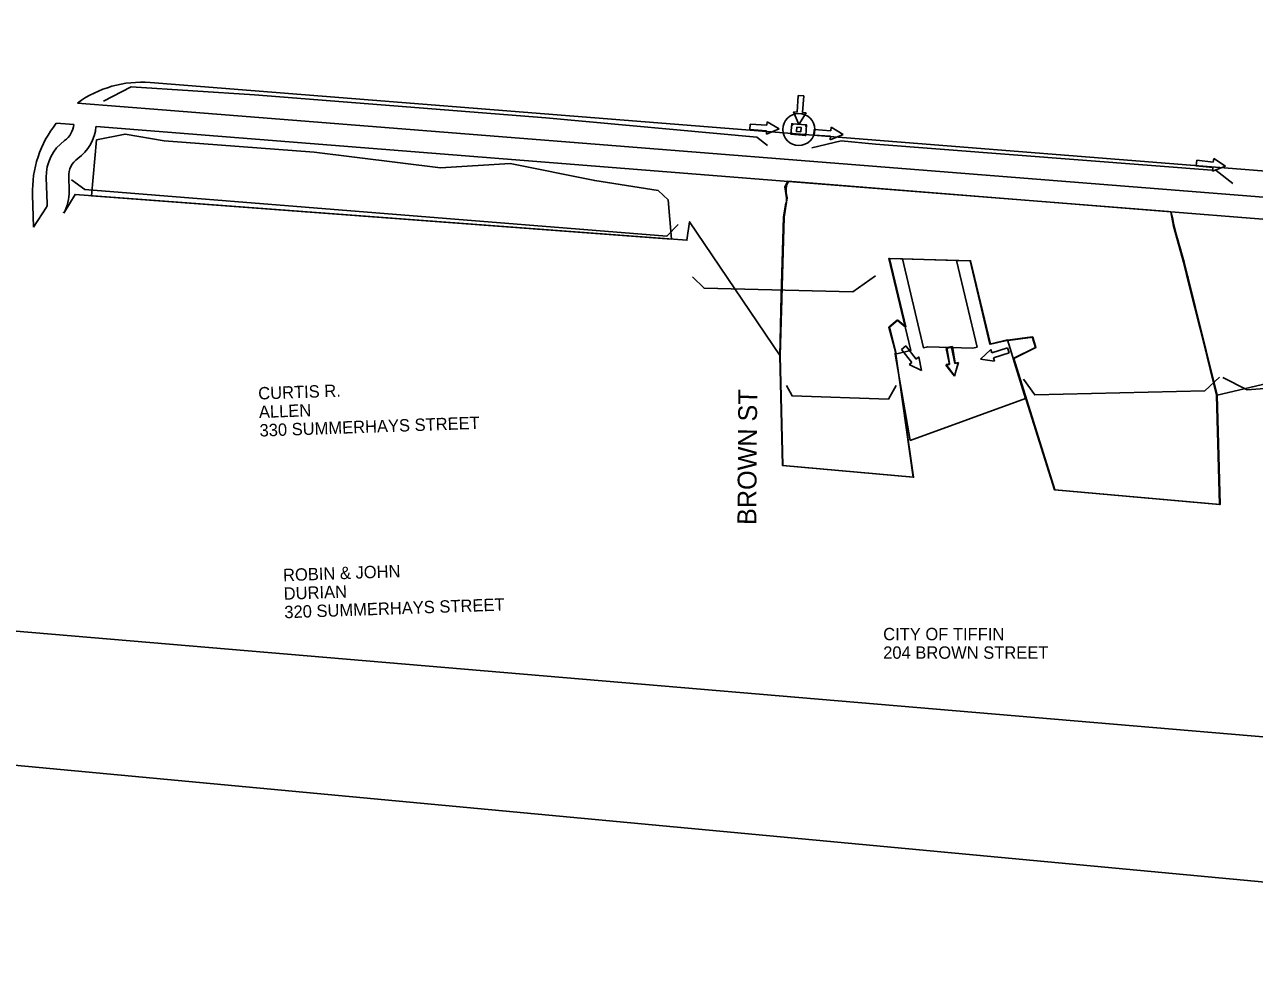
# Model space of a CAD drawing. Extents: x 20499351 to 20505779, y 7953198 to 7954637.
# Drawn here: x 20501297.9 to 20501580.1, y 7953706.6 to 7953921.8 of the extents above; entities that cross this region are included whole.
import ezdxf

# ---------------------------------------------------------------- set-up
doc = ezdxf.new("R2010")
doc.units = 0
for name, color, linetype in [('_CIVIL_CONSTRUCTION', 7, 'Continuous'), ('Contours Major', 7, 'Continuous'), ('Contours Minor', 7, 'Continuous'), ('NamedBoundary', 7, 'Continuous'), ('Sidewalk', 7, 'Continuous'), ('Terrain', 7, 'Continuous'), ('Terrains (working)', 7, 'Continuous'), ('TL_GroundIntercept', 7, 'Continuous')]:
    doc.layers.add(name, color=color, linetype=linetype)

msp = doc.modelspace()

# ---------------------------------------------------------------- linework, layer by layer
at = {"layer": '_CIVIL_CONSTRUCTION'}
for p, q in [((20501475.13, 7953901.75), (20501475.4, 7953905.56)), ((20501475.4, 7953905.56), (20501476.67, 7953905.47)), ((20501476.67, 7953905.47), (20501476.4, 7953901.66)), ((20501475.56, 7953898.85), (20501474.34, 7953901.81)), ((20501474.34, 7953901.81), (20501475.13, 7953901.75)), ((20501477.19, 7953901.6), (20501475.56, 7953898.85)), ((20501476.4, 7953901.66), (20501477.19, 7953901.6)), ((20501464.32, 7953897.7), (20501464.4, 7953898.97)), ((20501468.13, 7953897.46), (20501464.32, 7953897.7)), ((20501464.4, 7953898.97), (20501468.21, 7953898.73)), ((20501471.03, 7953897.91), (20501468.08, 7953896.66)), ((20501468.08, 7953896.66), (20501468.13, 7953897.46)), ((20501468.21, 7953898.73), (20501468.26, 7953899.52)), ((20501468.26, 7953899.52), (20501471.03, 7953897.91)), ((20501479, 7953896.45), (20501479.09, 7953897.72)), ((20501479.09, 7953897.72), (20501482.89, 7953897.45)), ((20501482.89, 7953897.45), (20501482.95, 7953898.24)), ((20501482.95, 7953898.24), (20501485.7, 7953896.61)), ((20501482.8, 7953896.18), (20501479, 7953896.45)), ((20501485.7, 7953896.61), (20501482.75, 7953895.39)), ((20501482.75, 7953895.39), (20501482.8, 7953896.18)), ((20501566.72, 7953889.41), (20501566.86, 7953890.67)), ((20501570.51, 7953888.99), (20501566.72, 7953889.41)), ((20501566.86, 7953890.67), (20501570.65, 7953890.26)), ((20501573.43, 7953889.32), (20501570.43, 7953888.2)), ((20501570.43, 7953888.2), (20501570.51, 7953888.99)), ((20501570.65, 7953890.26), (20501570.74, 7953891.05)), ((20501570.74, 7953891.05), (20501573.43, 7953889.32)), ((20501499.08, 7953847.26), (20501500.08, 7953848.05)), ((20501501.44, 7953844.27), (20501499.08, 7953847.26)), ((20501500.08, 7953848.05), (20501502.44, 7953845.05)), ((20501509.31, 7953847.5), (20501510.56, 7953847.76)), ((20501510.08, 7953843.77), (20501509.31, 7953847.5)), ((20501509.51, 7953847.69), (20501510.77, 7953847.9)), ((20501509.51, 7953847.69), (20501510.77, 7953847.9)), ((20501510.13, 7953843.93), (20501509.51, 7953847.69)), ((20501510.13, 7953843.93), (20501509.51, 7953847.69)), ((20501510.56, 7953847.76), (20501511.33, 7953844.02)), ((20501510.77, 7953847.9), (20501511.38, 7953844.13)), ((20501510.77, 7953847.9), (20501511.38, 7953844.13)), ((20501517.26, 7953845.03), (20501519.56, 7953847.26)), ((20501517.26, 7953845.03), (20501519.56, 7953847.26)), ((20501519.56, 7953847.26), (20501519.8, 7953846.5)), ((20501519.56, 7953847.26), (20501519.8, 7953846.5)), ((20501519.8, 7953846.5), (20501523.44, 7953847.66)), ((20501519.8, 7953846.5), (20501523.44, 7953847.66)), ((20501523.82, 7953846.44), (20501520.18, 7953845.29)), ((20501523.82, 7953846.44), (20501520.18, 7953845.29)), ((20501523.44, 7953847.66), (20501523.82, 7953846.44)), ((20501523.44, 7953847.66), (20501523.82, 7953846.44)), ((20501500.82, 7953843.77), (20501501.44, 7953844.27)), ((20501503.72, 7953842.41), (20501500.82, 7953843.77)), ((20501502.44, 7953845.05), (20501503.07, 7953845.55)), ((20501503.07, 7953845.55), (20501503.72, 7953842.41)), ((20501509.3, 7953843.61), (20501510.08, 7953843.77)), ((20501511.28, 7953841.09), (20501509.3, 7953843.61)), ((20501509.34, 7953843.8), (20501510.13, 7953843.93)), ((20501509.34, 7953843.8), (20501510.13, 7953843.93)), ((20501511.22, 7953841.21), (20501509.34, 7953843.8)), ((20501511.22, 7953841.21), (20501509.34, 7953843.8)), ((20501512.17, 7953844.26), (20501511.22, 7953841.21)), ((20501512.17, 7953844.26), (20501511.22, 7953841.21)), ((20501512.11, 7953844.18), (20501511.28, 7953841.09)), ((20501511.33, 7953844.02), (20501512.11, 7953844.18)), ((20501511.38, 7953844.13), (20501512.17, 7953844.26)), ((20501511.38, 7953844.13), (20501512.17, 7953844.26)), ((20501520.42, 7953844.53), (20501517.26, 7953845.03)), ((20501520.42, 7953844.53), (20501517.26, 7953845.03)), ((20501520.18, 7953845.29), (20501520.42, 7953844.53)), ((20501520.18, 7953845.29), (20501520.42, 7953844.53))]:
    msp.add_line(p, q, dxfattribs=at)
at = {"layer": 'Contours Major'}
for p, q in [((20501329.45, 7953902.27), (20501309.98, 7953903.81)), ((20501309.12, 7953898.87), (20501305.14, 7953899.18)), ((20501303.04, 7953880.67), (20501302.84, 7953886.71)), ((20501308.08, 7953883.63), (20501307.97, 7953886.87)), ((20501472.7, 7953882.09), (20501472.29, 7953884.6)), ((20501472.61, 7953884.04), (20501472.65, 7953883.18)), ((20501299.69, 7953882.76), (20501299.93, 7953875.35)), ((20501299.93, 7953875.35), (20501302.9, 7953879.88)), ((20501562.75, 7953871.57), (20501562.44, 7953872.68)), ((20501563.81, 7953867.26), (20501565.22, 7953861.59))]:
    msp.add_line(p, q, dxfattribs=at)
for points in [[(20501326.65, 7953908.51), (20501600.07, 7953886.78), (20501715.01, 7953876.49)], [(20501722.7, 7953869.06), (20501712.8, 7953870.66), (20501599.56, 7953880.8), (20501329.45, 7953902.27)], [(20501314.24, 7953898.46), (20501473.17, 7953885.83), (20501472.69, 7953884.91), (20501472.61, 7953884.04)], [(20501473.04, 7953885.84), (20501560.89, 7953878.86), (20501561.51, 7953875.58), (20501563.81, 7953867.26)], [(20501472.65, 7953883.18), (20501472.74, 7953882.63), (20501472.82, 7953882), (20501472.81, 7953881.92), (20501472.75, 7953881.58), (20501472.67, 7953881.08), (20501472.59, 7953880.54), (20501472.48, 7953879.86), (20501472.35, 7953879), (20501472.16, 7953877.56), (20501472.13, 7953877.64), (20501472.13, 7953877.64), (20501472.05, 7953874.77), (20501471.99, 7953872.4), (20501471.92, 7953869.84), (20501471.92, 7953869.84), (20501471.79, 7953864.93), (20501471.7, 7953861.7), (20501471.55, 7953856.05), (20501471.43, 7953851.79), (20501471.27, 7953845.76), (20501450.45, 7953876.55), (20501449.84, 7953872.33), (20501309.45, 7953882.82), (20501306.86, 7953878.51)], [(20501565.22, 7953861.59), (20501567.61, 7953852.01), (20501569.22, 7953845.56), (20501571.41, 7953836.75), (20501572.08, 7953811.64), (20501534.19, 7953815.03), (20501524.72, 7953845.2), (20501529.83, 7953847.71), (20501529.09, 7953850.11), (20501523.45, 7953849.35), (20501523.43, 7953849.43), (20501519.35, 7953848.49), (20501514.82, 7953867.61), (20501496.2, 7953868.15), (20501499.92, 7953852.43), (20501498.08, 7953853.98), (20501496.18, 7953852.35), (20501497.69, 7953846.67), (20501501.74, 7953817.94), (20501471.76, 7953820.62), (20501471.14, 7953845.77), (20501471.51, 7953859.67), (20501472, 7953877.65), (20501472.23, 7953879.1), (20501472.44, 7953880.48)], [(20501560.89, 7953878.86), (20501599.27, 7953875.81), (20501712.32, 7953865.69), (20501724.43, 7953863.89)], [(20501722.45, 7953841.98), (20501709.69, 7953845.42), (20501604.77, 7953844.53), (20501571.55, 7953836.74), (20501570.62, 7953840.47), (20501565.52, 7953860.92)]]:
    msp.add_lwpolyline(points, dxfattribs=at)
for centre, radius, start, end in [((20501324.67, 7953883.59), 25, 85.4564, 125.9922), ((20501324.67, 7953883.59), 25, 141.4006, 181.902), ((20501304.14, 7953899.26), 5, 305.4398, 355.4564), ((20501304.27, 7953899.25), 10, 305.4398, 355.4564), ((20501312.83, 7953887.04), 10, 125.4398, 181.902), ((20501312.97, 7953887.03), 5, 125.4398, 181.902), ((20501513.19, 7953860.93), 47.26, 148.1884, 149.936), ((20501298.08, 7953883.3), 10, 331.4231, 1.902), ((20501472.3, 7953884.6), 0.011, 149.936, 189.1729), ((20501469.48, 7953881.78), 3.24, 336.4173, 5.6454), ((20501642.03, 7953896.12), 82.96, 192.0078, 195.679), ((20501542.49, 7953867.71), 20.56, 13.9654, 16.9246), ((20501209.32, 7953773.92), 366.67, 13.7258, 15.445)]:
    msp.add_arc(centre, radius, start, end, dxfattribs=at)
at = {"layer": 'Contours Minor'}
for p, q in [((20501473.89, 7953898.74), (20501474.06, 7953898.72)), ((20501474.06, 7953898.72), (20501474.24, 7953898.88)), ((20501474.25, 7953899.05), (20501474.24, 7953898.88)), ((20501476.79, 7953896.41), (20501476.81, 7953896.57)), ((20501476.99, 7953896.73), (20501476.81, 7953896.57)), ((20501477.16, 7953896.71), (20501476.99, 7953896.73)), ((20501472.63, 7953884.51), (20501472.69, 7953884.91)), ((20501561.35, 7953877.13), (20501561.6, 7953875.8)), ((20501499.3, 7953868.06), (20501496.2, 7953868.15)), ((20501511.71, 7953867.7), (20501499.3, 7953868.06)), ((20501514.82, 7953867.61), (20501511.71, 7953867.7)), ((20501514.82, 7953867.61), (20501511.71, 7953867.7))]:
    msp.add_line(p, q, dxfattribs=at)
for points in [[(20501468.37, 7953894.06), (20501465.9, 7953895.97), (20501417.47, 7953900.44), (20501350.62, 7953905.7), (20501322.3, 7953907.56), (20501315.97, 7953904.21)], [(20501575.15, 7953885.36), (20501571.31, 7953888.3), (20501493.12, 7953894.4), (20501485.21, 7953895.11), (20501478.54, 7953893.5)], [(20501447.85, 7953875.9), (20501445.26, 7953873.24), (20501311.64, 7953883.94), (20501308.6, 7953886.15)], [(20501473.17, 7953885.83), (20501560.38, 7953878.9), (20501560.89, 7953878.86), (20501561.35, 7953877.13)], [(20501561.6, 7953875.8), (20501562.16, 7953873.7), (20501563.94, 7953867.25), (20501571.55, 7953836.74), (20501572.21, 7953811.63), (20501534.32, 7953815.02), (20501524.85, 7953845.18), (20501529.96, 7953847.7), (20501529.23, 7953850.1), (20501523.59, 7953849.34), (20501523.56, 7953849.42), (20501519.49, 7953848.48), (20501514.95, 7953867.6), (20501496.33, 7953868.14), (20501500.06, 7953852.42), (20501498.22, 7953853.97), (20501496.31, 7953852.34), (20501497.83, 7953846.65), (20501497.76, 7953846.15), (20501501.87, 7953817.92), (20501471.89, 7953820.61), (20501471.27, 7953845.76), (20501472.13, 7953877.64), (20501472.83, 7953882.08), (20501472.65, 7953883.18)], [(20501499.3, 7953868.06), (20501496.2, 7953868.15), (20501499.92, 7953852.43)], [(20501496.2, 7953868.15), (20501501.21, 7953846.99), (20501497.62, 7953846.16), (20501501.11, 7953826.36)], [(20501511.71, 7953867.7), (20501516.43, 7953847.81), (20501515.46, 7953847.58), (20501505.11, 7953847.88), (20501504.14, 7953847.65), (20501499.3, 7953868.06)], [(20501523.45, 7953849.35), (20501523.43, 7953849.43), (20501519.35, 7953848.49), (20501514.82, 7953867.61)], [(20501527.52, 7953835.96), (20501523.43, 7953849.43), (20501519.35, 7953848.49), (20501514.82, 7953867.61)], [(20501451.16, 7953863.93), (20501453.78, 7953861.31), (20501487.9, 7953860.48), (20501493.13, 7953864.17)], [(20501499.92, 7953852.43), (20501498.08, 7953853.98), (20501496.18, 7953852.35), (20501497.69, 7953846.67)], [(20501524.72, 7953845.2), (20501529.83, 7953847.71), (20501529.09, 7953850.11), (20501523.45, 7953849.35)], [(20501497.69, 7953846.67), (20501497.62, 7953846.16), (20501501.11, 7953826.36), (20501527.52, 7953835.96), (20501524.72, 7953845.2)], [(20501527.1, 7953840.45), (20501529.67, 7953836.83), (20501568.67, 7953837.78), (20501572.09, 7953840.92)], [(20501624.22, 7953843.19), (20501619.62, 7953841.11), (20501578.45, 7953837.98), (20501572.8, 7953840.81)], [(20501472.68, 7953838.95), (20501473.99, 7953836.57), (20501496.11, 7953835.86), (20501497.89, 7953838.95)], [(20501501.11, 7953826.36), (20501527.52, 7953835.96)]]:
    msp.add_lwpolyline(points, dxfattribs=at)
for points in [[(20501473.72, 7953896.65), (20501477.13, 7953896.38), (20501477.32, 7953898.8), (20501473.92, 7953899.07)], [(20501473.92, 7953899.07), (20501477.32, 7953898.8), (20501477.13, 7953896.38), (20501473.72, 7953896.65)], [(20501473.89, 7953896.64), (20501473.72, 7953896.65), (20501473.75, 7953896.99), (20501473.92, 7953896.98)], [(20501474.06, 7953898.72), (20501473.89, 7953898.74), (20501473.92, 7953899.07), (20501474.09, 7953899.06)], [(20501475.06, 7953898.27), (20501476.07, 7953898.19), (20501475.99, 7953897.18), (20501474.98, 7953897.26)], [(20501477.3, 7953898.46), (20501477.13, 7953898.48), (20501477.16, 7953898.81), (20501477.32, 7953898.8)], [(20501477.13, 7953896.38), (20501476.96, 7953896.39), (20501476.99, 7953896.73), (20501477.16, 7953896.71)]]:
    msp.add_lwpolyline(points, close=True, dxfattribs=at)
msp.add_circle((20501475.52, 7953897.73), 3.66, dxfattribs=at)
for centre, radius, start, end in [((20501476.27, 7953883.62), 3.81, 144.5885, 160.2487), ((20501479.46, 7953883.95), 6.85, 175.3443, 186.4382), ((20501301.04, 7953880.61), 2, 339.1831, 1.902), ((20501312.26, 7953876.02), 6.06, 153.0181, 154.7508)]:
    msp.add_arc(centre, radius, start, end, dxfattribs=at)
at = {"layer": 'NamedBoundary'}
msp.add_lwpolyline([(20501161.33, 7954095.04), (20501136.01, 7953796.11), (20502073.14, 7953716.74), (20502098.46, 7954015.67)], close=True, dxfattribs=at)
at = {"layer": 'Sidewalk'}
for centre, radius, start, end in [((20501301.04, 7953880.61), 2, 339.1831, 1.902), ((20501312.26, 7953876.02), 6.06, 153.0181, 154.7508)]:
    msp.add_arc(centre, radius, start, end, dxfattribs=at)
at = {"layer": 'Terrain'}
msp.add_lwpolyline([(20501791.06, 7953833.84), (20501779.66, 7953706.56), (20499351.13, 7953933.78), (20499411.85, 7954636.65), (20501855.07, 7954405.25), (20501814.1, 7954091.19), (20501791.1, 7953834.34)], dxfattribs=at)
at = {"layer": 'Terrains (working)'}
msp.add_lwpolyline([(20501313.18, 7953882.54), (20501314.37, 7953895.33), (20501320.91, 7953896.68), (20501329.91, 7953895.14), (20501364.27, 7953892.51), (20501393.33, 7953888.95), (20501409.25, 7953889.9), (20501428.69, 7953886.02), (20501443.22, 7953883.77), (20501445.56, 7953881.58), (20501446.34, 7953872.59)], close=True, dxfattribs=at)

# ---------------------------------------------------------------- texts
at = {"layer": 'TL_GroundIntercept'}
for s, height, rotation, p in [('CURTIS R.', 2.835, 2.0248, (20501351.52, 7953835.75)), ('BROWN ST', 4.32, 89.5632, (20501465.75, 7953806.96)), ('ALLEN', 2.835, 2.0248, (20501351.67, 7953831.5)), ('330 SUMMERHAYS STREET', 2.8346, 2.0248, (20501351.82, 7953827.25)), ('ROBIN & JOHN', 2.8346, 2.0248, (20501357.21, 7953794.04)), ('DURIAN', 2.835, 2.0248, (20501357.36, 7953789.79)), ('320 SUMMERHAYS STREET', 2.8346, 2.0248, (20501357.51, 7953785.54))]:
    msp.add_text(s, height=height, rotation=rotation, dxfattribs=at).set_placement(p)
for s, p in [('CITY OF TIFFIN', (20501494.89, 7953780.51)), ('204 BROWN STREET', (20501494.89, 7953776.26))]:
    msp.add_text(s, height=2.8346, dxfattribs=at).set_placement(p)

doc.saveas('drawing.dxf')
